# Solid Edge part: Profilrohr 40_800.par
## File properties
Username: ahadarics
Dokumentum tartalom típus: 0
Author: ahadarics
Last saved by: ahadarics
Revision: 97
Sűrűség: 0,000 kg/m^3
Pontosság: 0,990
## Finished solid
Body 1: solid body, 175 faces, 519 edges, 346 vertices.
  Faces by surface: cylinder 107, plane 68
  Edges by curve: line 305, circle 214
Bounding box of the edges (mm): 51.354 x 51.354 x 843.000, from (-25.6768, -25.6768, -734) to (25.6768, 25.6768, 109).
Cylindrical faces by radius (mm): R0.1 x16, R0.2 x30, R0.5 x28, R1 x8, R2.7 x8, R3.5 x4, R5 x4, R20 x1, R22 x8
Planar faces by outward normal: +x 6, +y 6, +z 1, -x 4, -y 4, -z 1, oblique 46
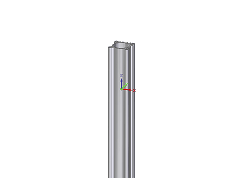
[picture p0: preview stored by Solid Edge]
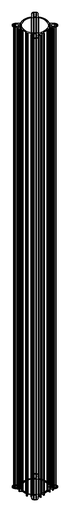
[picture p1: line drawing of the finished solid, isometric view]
